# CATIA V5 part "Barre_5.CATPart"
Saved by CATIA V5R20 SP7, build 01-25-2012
Part number: Barre_5
Bounding box of the stored display mesh (mm): x -2 to 0, y 17.005 to 28.95, z -0.995 to 1.948
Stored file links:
  J:\IFMA\IAO\système avant mef\Barre_5.CATPart
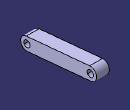
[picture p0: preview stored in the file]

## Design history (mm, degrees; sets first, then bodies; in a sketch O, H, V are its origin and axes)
Body1 (main body)
  Plane1: stored without definition
  Plane2: stored without definition
  Point1 "Point.C": stored without definition
  Point2 "Point.B": stored without definition
  Sketch1 on Plane1, origin (-2, 0, 0), H (0, 1, 0), V (0, 0, 1)
    construction line L1 (18, 0) -> (27.9546, 0.9521)
    point P1 (18, 0)
    point P2 (27.9546, 0.9521)
    line L2 (17.9048, 0.9955) -> (27.8594, 1.9476)
    line L3 (28.0498, -0.0433) -> (18.0952, -0.9955)
    arc A1 centre (27.9546, 0.9521) radius 1 from (27.8594, 1.9476) to (28.0498, -0.0433) cw
    arc A2 centre (18, 0) radius 1 from (18.0952, -0.9955) to (17.9048, 0.9955) cw
    reference projected point E1 (18, 0) from Point1
    reference projected point E2 (27.9546, 0.9521) from Point2
    distance L1 L2 = 1
    tangency: A1 L2, A2 L2, A1 L3, A2 L3
    coincidence: P1 E1, P2 E2
  Pad1: profile Sketch1, direction (1, 0, 0), length 2
  Sketch2 on start face of Pad1, origin (-2, 18.6085, -0.4705), H (0, 1, 0), V (0, 0, -1)
    point P1 (-0.6085, -0.4705)
    reference projected point E1 (-0.6085, -0.4705) from Point3
    coincidence: P1 E1
  Hole1: placed by Sketch2, at (-2, 18, 0) direction (1, 0, 0), diameter 1, through (limit type 3)
  Sketch3 on start face of Pad1, origin (-2, 26.8803, 1.1173), H (0, 1, 0), V (0, 0, -1)
    point P1 (1.0743, 0.1652)
    reference projected point E1 (1.0743, 0.1652) from Point4
    coincidence: P1 E1
  Hole2: placed by Sketch3, at (-2, 27.9546, 0.9521) direction (1, 0, 0), diameter 1, through (limit type 3)
  Point3 "Point.C": stored without definition
  Point4 "Point.B": stored without definition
